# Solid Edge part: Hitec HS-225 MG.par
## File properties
Author: nakano
Template: iso metric part.par
Last saved by: nakano
Revision: 2
Application: Solid Edge
Accuracy: 0.990
Username: nakano
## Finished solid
Body 1: solid body, 300 faces, 736 edges, 439 vertices.
  Faces by surface: plane 118, cylinder 102, torus 51, sphere 16, spline 12, cone 1
  Edges by curve: line 430, circle 268, curve on surface 16, spline 12, ellipse 5, intersection 5
Bounding box of the edges (mm; curved faces can reach further): 44.070 x 36.280 x 16.770, from (-22.035, -23.69, -8.385) to (22.035, 12.59, 8.385).
Cylindrical faces by radius (mm): R0.5 x70, R1 x24, R1.25 x1, R2.225 x4, R6 x1, R7.5 x2
Conical faces (half-angle, radius in mm at the cone's reference point): 59 deg R1.25 x1
Toroidal faces (ring radius, tube radius in mm): R0.5 r0.5 x25, R1 r0.5 x4, R1.5 r0.5 x12, R2.725 r0.5 x4, R5.5 r0.5 x1, R6.5 r0.5 x1, R7 r0.5 x2, R8 r0.5 x2
Spherical faces by radius (mm): R0.5 x16
Planar faces by outward normal: +x 9, +y 13, +z 9, -x 9, -y 3, -z 9, oblique 66
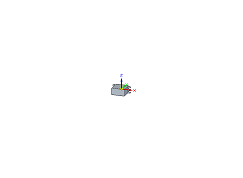
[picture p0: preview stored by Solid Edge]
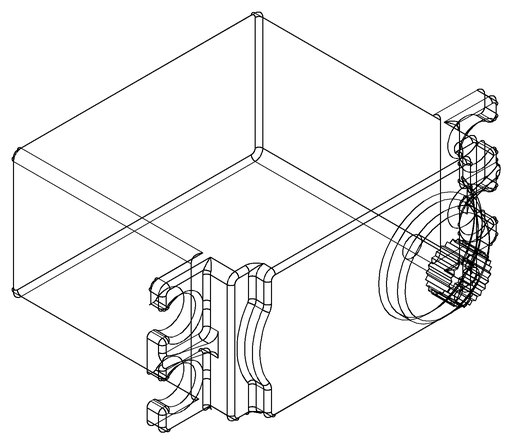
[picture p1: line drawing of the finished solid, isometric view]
